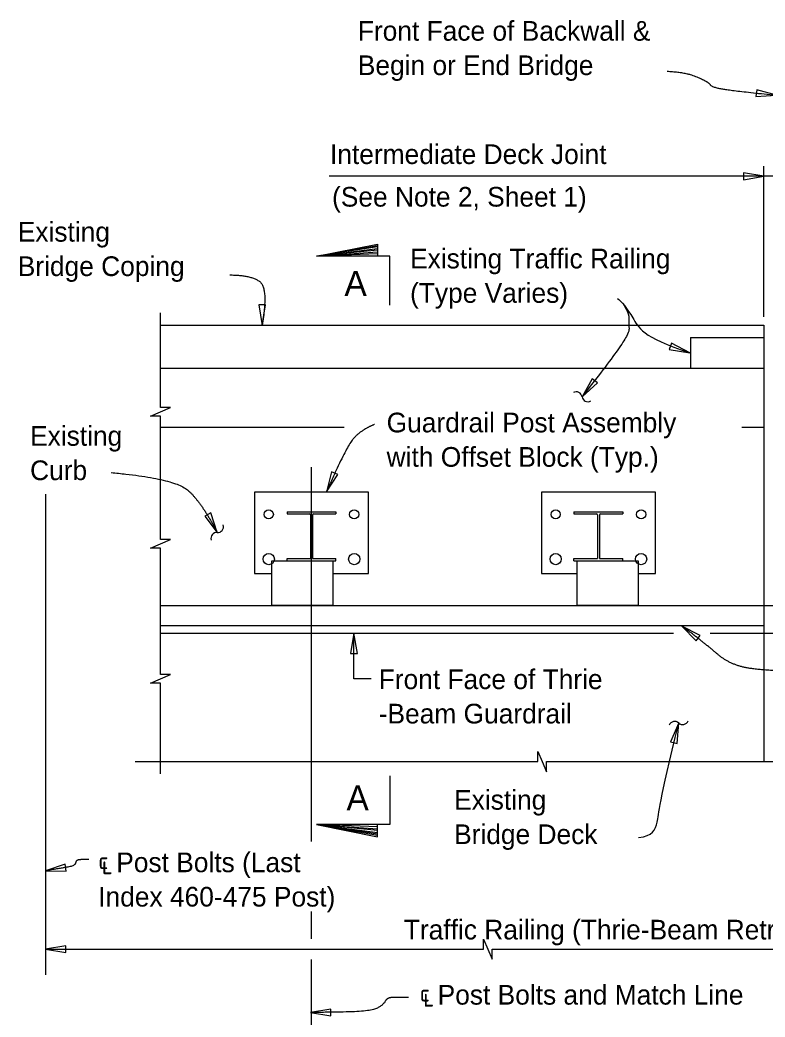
# Model space of a CAD drawing. Extents: x 21587 to 21659.1, y 56113.9 to 56155.9.
# Drawn here: x 21605.87 to 21613.5, y 56142.64 to 56152.85 of the extents above; entities that cross this region are included whole.
import ezdxf

# ---------------------------------------------------------------- set-up
doc = ezdxf.new("R2010")
doc.units = 0
for name, color, linetype in [('AdhocPoint_dp', 7, 'Continuous'), ('Border', 7, 'Continuous'), ('PlotBorder_dp', 7, 'Continuous'), ('SheetBorder_dp', 7, 'Continuous'), ('TextMisc', 7, 'Continuous')]:
    doc.layers.add(name, color=color, linetype=linetype)

msp = doc.modelspace()

# ---------------------------------------------------------------- linework, layer by layer
at = {"layer": 'AdhocPoint_dp'}
for p, q in [((21613.488, 56149.72), (21607.312, 56149.72)), ((21613.488, 56149.722), (21613.488, 56145.254)), ((21612.738, 56149.595), (21613.488, 56149.595)), ((21607.312, 56149.282), (21613.488, 56149.282)), ((21607.312, 56148.678), (21609.192, 56148.678)), ((21613.265, 56148.678), (21613.488, 56148.678)), ((21607.312, 56146.648), (21613.488, 56146.648))]:
    msp.add_line(p, q, dxfattribs=at)
msp.add_lwpolyline([(21612.738, 56149.595), (21612.738, 56149.282)], dxfattribs=at)
at = {"layer": 'Border'}
for p, q in [((21608.608, 56147.811), (21609.108, 56147.811)), ((21608.608, 56147.811), (21608.608, 56147.79)), ((21608.608, 56147.79), (21608.837, 56147.79)), ((21608.848, 56147.78), (21608.848, 56147.332)), ((21608.868, 56147.78), (21608.868, 56147.332)), ((21608.879, 56147.79), (21609.108, 56147.79)), ((21609.108, 56147.811), (21609.108, 56147.79)), ((21611.545, 56147.811), (21612.045, 56147.811)), ((21611.545, 56147.811), (21611.545, 56147.79)), ((21611.545, 56147.79), (21611.775, 56147.79)), ((21611.785, 56147.78), (21611.785, 56147.332)), ((21611.806, 56147.78), (21611.806, 56147.332)), ((21611.816, 56147.79), (21612.045, 56147.79)), ((21612.045, 56147.811), (21612.045, 56147.79)), ((21608.608, 56147.332), (21608.848, 56147.332)), ((21608.608, 56147.311), (21608.608, 56147.332)), ((21608.608, 56147.311), (21609.108, 56147.311)), ((21608.868, 56147.332), (21609.108, 56147.332)), ((21609.108, 56147.311), (21609.108, 56147.332)), ((21611.545, 56147.332), (21611.785, 56147.332)), ((21611.545, 56147.311), (21611.545, 56147.332)), ((21611.545, 56147.311), (21612.045, 56147.311)), ((21611.806, 56147.332), (21612.045, 56147.332)), ((21612.045, 56147.311), (21612.045, 56147.332)), ((21607.312, 56146.851), (21619.379, 56146.851)), ((21607.312, 56146.57), (21612.565, 56146.57)), ((21612.941, 56146.57), (21619.379, 56146.57))]:
    msp.add_line(p, q, dxfattribs=at)
for points in [[(21609.077, 56147.181), (21609.441, 56147.181), (21609.441, 56148.014), (21608.275, 56148.014), (21608.275, 56147.181), (21608.452, 56147.181)], [(21612.202, 56147.181), (21612.379, 56147.181), (21612.379, 56148.014), (21611.212, 56148.014), (21611.212, 56147.181), (21611.577, 56147.181)]]:
    msp.add_lwpolyline(points, dxfattribs=at)
for centre, radius in [((21608.42, 56147.785), 0.0469), ((21609.295, 56147.785), 0.0469), ((21611.358, 56147.785), 0.0469), ((21612.233, 56147.785), 0.0469), ((21608.42, 56147.327), 0.0573), ((21609.295, 56147.327), 0.0573), ((21611.358, 56147.327), 0.0573), ((21612.233, 56147.327), 0.0573)]:
    msp.add_circle(centre, radius, dxfattribs=at)
for centre, start, end in [((21608.837, 56147.78), 0, 90), ((21608.879, 56147.78), 90, 180), ((21611.775, 56147.78), 0, 90), ((21611.816, 56147.78), 90, 180)]:
    msp.add_arc(centre, 0.0104, start, end, dxfattribs=at)
at = {"layer": 'PlotBorder_dp'}
for p, q in [((21613.488, 56149.808), (21613.488, 56151.352)), ((21613.996, 56151.248), (21609.039, 56151.248)), ((21608.91, 56150.429), (21609.535, 56150.539)), ((21609.535, 56150.526), (21608.91, 56150.429)), ((21608.91, 56150.429), (21609.535, 56150.509)), ((21609.535, 56150.491), (21608.91, 56150.429)), ((21608.91, 56150.429), (21609.535, 56150.473)), ((21609.535, 56150.453), (21608.91, 56150.429)), ((21608.858, 56144.434), (21608.858, 56148.27)), ((21609.535, 56144.586), (21608.91, 56144.609)), ((21608.91, 56144.609), (21609.535, 56144.566)), ((21609.535, 56144.547), (21608.91, 56144.609)), ((21608.91, 56144.609), (21609.535, 56144.529)), ((21609.535, 56144.512), (21608.91, 56144.609)), ((21608.91, 56144.609), (21609.535, 56144.499)), ((21608.858, 56143.438), (21608.858, 56143.72)), ((21608.858, 56135.158), (21608.858, 56143.226))]:
    msp.add_line(p, q, dxfattribs=at)
for points in [[(21613.62, 56152.078), (21613.416, 56152.134), (21613.409, 56152.064)], [(21613.488, 56151.248), (21613.28, 56151.283), (21613.28, 56151.212)], [(21608.352, 56149.721), (21608.388, 56149.93), (21608.317, 56149.93)], [(21612.73, 56149.441), (21612.543, 56149.539), (21612.521, 56149.472)], [(21611.628, 56148.989), (21611.785, 56149.131), (21611.73, 56149.175)], [(21609.011, 56148.015), (21609.126, 56148.192), (21609.061, 56148.22)], [(21607.893, 56147.6), (21607.828, 56147.801), (21607.765, 56147.768)], [(21609.292, 56146.57), (21609.257, 56146.361), (21609.327, 56146.361)], [(21612.651, 56146.642), (21612.796, 56146.489), (21612.839, 56146.546)], [(21612.618, 56145.649), (21612.534, 56145.455), (21612.602, 56145.438)], [(21606.135, 56144.136), (21606.346, 56144.133), (21606.335, 56144.203)], [(21606.135, 56143.332), (21606.343, 56143.297), (21606.343, 56143.368)], [(21608.848, 56142.685), (21609.056, 56142.65), (21609.056, 56142.72)]]:
    msp.add_lwpolyline(points, close=True, dxfattribs=at)
for points in [[(21609.66, 56149.929), (21609.66, 56150.429), (21608.91, 56150.429), (21609.535, 56150.554), (21609.535, 56150.429)], [(21607.312, 56148.322), (21607.312, 56148.791), (21607.208, 56148.791), (21607.312, 56148.836), (21607.415, 56148.881), (21607.312, 56148.881), (21607.312, 56149.85)], [(21607.312, 56146.575), (21607.312, 56147.438), (21607.208, 56147.438), (21607.312, 56147.483), (21607.415, 56147.528), (21607.312, 56147.528), (21607.312, 56148.322)], [(21607.312, 56145.128), (21607.312, 56146.056), (21607.208, 56146.056), (21607.312, 56146.101), (21607.415, 56146.146), (21607.312, 56146.146), (21607.312, 56147.019)], [(21607.053, 56145.254), (21611.175, 56145.254), (21611.175, 56145.357), (21611.22, 56145.254), (21611.265, 56145.15), (21611.265, 56145.254), (21613.496, 56145.254)], [(21613.496, 56145.254), (21617.776, 56145.254), (21617.776, 56145.357), (21617.821, 56145.254), (21617.866, 56145.15), (21617.866, 56145.254), (21620.131, 56145.254)], [(21609.66, 56145.109), (21609.66, 56144.609), (21608.91, 56144.609), (21609.535, 56144.484), (21609.535, 56144.609)], [(21606.135, 56143.332), (21610.618, 56143.332), (21610.618, 56143.436), (21610.663, 56143.332), (21610.708, 56143.229), (21610.708, 56143.332), (21626.014, 56143.332)]]:
    msp.add_lwpolyline(points, dxfattribs=at)
for centre, start, end in [((21611.569, 56148.981), 8.6098, 120.3371), ((21611.687, 56148.999), 188.6098, 300.3371), ((21607.888, 56147.54), 85.5858, 197.313), ((21607.897, 56147.659), 265.5858, 17.313), ((21612.577, 56145.605), 47.1839, 158.9112), ((21612.658, 56145.692), 227.1839, 338.9112)]:
    msp.add_arc(centre, 0.0596, start, end, dxfattribs=at)
for points, degree in [([(21612.498, 56152.323), (21612.683, 56152.316), (21612.921, 56152.217), (21612.954, 56152.158), (21613.224, 56152.118), (21613.62, 56152.078)], 2), ([(21608.02, 56150.237), (21608.232, 56150.237), (21608.418, 56150.106), (21608.352, 56149.721)], 2), ([(21612.049, 56149.941), (21612.108, 56149.846), (21612.108, 56149.749), (21612.108, 56149.595), (21611.628, 56148.989)], 2), ([(21611.99, 56149.997), (21612.024, 56149.973), (21612.164, 56149.808), (21612.239, 56149.6), (21612.73, 56149.441)], 3), ([(21609.504, 56148.707), (21609.371, 56148.652), (21609.217, 56148.489), (21609.011, 56148.015)], 2), ([(21606.807, 56148.213), (21607.461, 56148.155), (21607.738, 56147.897), (21607.893, 56147.6)], 2), ([(21609.47, 56146.101), (21609.292, 56146.101), (21609.292, 56146.101), (21609.292, 56146.411), (21609.292, 56146.57)], 2), ([(21613.905, 56146.18), (21613.496, 56146.18), (21613.139, 56146.246), (21612.888, 56146.464), (21612.651, 56146.642)], 2), ([(21612.207, 56144.475), (21612.35, 56144.493), (21612.413, 56144.611), (21612.413, 56144.821), (21612.618, 56145.649)], 3), ([(21606.577, 56144.252), (21606.511, 56144.251), (21606.447, 56144.245), (21606.438, 56144.188), (21606.312, 56144.164), (21606.135, 56144.136)], 2), ([(21609.851, 56142.837), (21609.731, 56142.837), (21609.632, 56142.837), (21609.59, 56142.756), (21609.456, 56142.695), (21609.01, 56142.685), (21608.848, 56142.685)], 2)]:
    msp.add_open_spline(points, degree=degree, dxfattribs=at)
at = {"layer": 'TextMisc'}
msp.add_line((21606.135, 56147.992), (21606.135, 56143.07), dxfattribs=at)
for points in [[(21609.077, 56147.311), (21609.077, 56146.853), (21608.452, 56146.853), (21608.452, 56147.311)], [(21612.202, 56147.311), (21612.202, 56146.853), (21611.577, 56146.853), (21611.577, 56147.311)]]:
    msp.add_lwpolyline(points, close=True, dxfattribs=at)

# ---------------------------------------------------------------- texts
at = {"layer": 'PlotBorder_dp'}
for s, p in [('Front Face of Backwall &', (21609.332, 56152.636)), ('Begin or End Bridge', (21609.332, 56152.284)), ('Existing ', (21605.85, 56150.578)), ('Bridge Coping ', (21605.85, 56150.226)), ('Existing Traffic Railing', (21609.867, 56150.304)), ('(Type Varies)', (21609.867, 56149.952)), ('Guardrail Post Assembly ', (21609.627, 56148.625)), ('Existing ', (21605.976, 56148.488)), ('with Offset Block (Typ.)', (21609.627, 56148.273)), ('Curb', (21605.976, 56148.136)), ('Front Face of Thrie', (21609.546, 56145.996)), ('-Beam Guardrail', (21609.546, 56145.644)), ('Existing ', (21610.318, 56144.761)), ('Bridge Deck', (21610.318, 56144.409)), ('℄ Post Bolts (Last', (21606.674, 56144.121)), ('Index 460-475 Post)', (21606.674, 56143.769)), ('℄ Post Bolts and Match Line', (21609.965, 56142.765))]:
    msp.add_text(s, height=0.2016, dxfattribs=at).set_placement(p)
at = {"layer": 'SheetBorder_dp'}
for s, height, p in [('Intermediate Deck Joint', 0.2016, (21609.047, 56151.373)), ('(See Note 2, Sheet 1)', 0.2016, (21609.068, 56150.937)), ('A', 0.256, (21609.195, 56150.023)), ('A', 0.256, (21609.216, 56144.754)), ('Traffic Railing (Thrie-Beam Retrofit) Limits of Payment', 0.2016, (21609.803, 56143.432))]:
    msp.add_text(s, height=height, dxfattribs=at).set_placement(p)

doc.saveas('drawing.dxf')
